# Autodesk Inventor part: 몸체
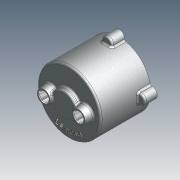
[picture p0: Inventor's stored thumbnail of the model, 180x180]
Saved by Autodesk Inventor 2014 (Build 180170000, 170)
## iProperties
Company: 한국ATC센터
Created: 2012-05
Part Number: 몸체
Document SubType Name: 모델링
Designer: KYOUNG IL JANG
Mass: 471.062 g
Surface Area: 679.308 cm^2
Volume: 173.824 cm^3
Density: 2.71 g/cm^3
Material: 알루미늄-6061
Appearance: 알루미늄 - 평지
변환 표준: STEP AP214IS
파일 이름: C:\Users\SeoGD\Desktop\?쒗뿕\紐몄껜.stp
전처리기: Build: 253, Release: 2010 SP1 - Date: Wed 07/29/2009
전송 단위: 밀리미터
불확실성: 0.01
Author: KYOUNG IL JANG
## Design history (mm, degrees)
sketch "스케치2"
  geometry: C1 r 50 at (0, 0); 1 further point
  constraints: 1 centre point, 1 coincident
  dimensions: "d9" = 100 diameter of C1
extrude "돌출2" new body sketch "스케치2" distance "d10" = 80; taper "d11" = 0 deg
feature "쉘1" dims "d12" = 5
sketch "스케치3" dims "d13" = 55
  geometry: C1 r 7.5 at (27.5, 0); C2 r 12.5 at (27.5, 0); 2 further points
  constraints: 2 centre point, 2 coincident, 2 horizontal alignment, 2 other
  dimensions: "d14" = 15 diameter of C1; "d15" = 25 diameter of C2
extrude "돌출3" join sketch "스케치3" distance "d16" = 12; taper "d17" = -10 deg
hole "구멍2" diameter "d20" = 15; stored, may be unused: countersink angle "d24" = 90 deg, drill point angle "d26" = 118 deg; dims "d18" = 10, "d19" = 10, "d21" = 6, "d22" = 4, "d23" = 2, "d25" = 15
chamfer "모따기1" distance "d27" = 1; stored, may be unused: second distance "d28" = 2, angle "d29" = 45 deg
sketch "스케치4"
  geometry: L1 (0, 0)-(0, 88); L2 (0, 70)-(13.16, 70); L3 (-45, 75)-(45, 75) reference; L4 (-50, 80)-(50, 80) reference; L5 (13.16, 70)-(14.5, 75); L6 (20, 80)-(20, 88); L7 (20, 88)-(0, 88); L8 (20, 80)-(14.5, 75)
  constraints: 12 end point, 3 point on line, 2 perpendicular, 1 vertical
  dimensions: "d34" = 40 diameter of L6 L1; "d35" = 105 deg angle of L5 L3; "d36" = 5 distance between parallel lines of L2 L3; "d37" = 8 distance between parallel lines of L7 L4; "d51" = 29 diameter of L5.end L1
revolve "회전1" sketch "스케치4" stored, may be unused: angle "d38" = 90 deg
hole "구멍3" diameter "d41" = 15; stored, may be unused: countersink angle "d45" = 90 deg, drill point angle "d47" = 0 deg; dims "d39" = 10, "d40" = 10, "d42" = 6, "d43" = 22, "d44" = 13, "d46" = 15
chamfer "모따기2" distance "d48" = 1; stored, may be unused: second distance "d49" = 2, angle "d50" = 45 deg
fillet "모깎기1" dims "d52" = 3
fillet "모깎기2" dims "d53" = 3, "d72" = 0.2
sketch "스케치5"
  geometry: A1 r 50 centre (0, 0) between (50, 0) and (-8.074, 49.344) reference; A2 r 8.5 centre (0, 52) between (8.074, 49.344) and (-8.074, 49.344); 1 further point
  constraints: 5 point on circle, 1 centre point, 1 horizontal alignment
  dimensions: "d54" = 90 deg dimension on point (0, 0) A2.centre A1.start; "d55" = 52 distance of A2.centre point (0, 0); "d56" = 17 diameter of A2
extrude "돌출4" join sketch "스케치5" distance "d57" = 20; taper "d58" = 0 deg
fillet "모깎기3" dims "d59" = 3
hole "구멍4" diameter "d62" = 4.134; stored, may be unused: countersink angle "d66" = 90 deg, drill point angle "d68" = 118 deg; dims "d60" = 10, "d61" = 10, "d63" = 12, "d64" = 22, "d65" = 13, "d67" = 15
sketch "스케치6"
  geometry: C1 r 47 at (0, 0) reference; C2 r 42.5 at (0, 0); 1 further point
  constraints: 1 centre point, 1 coincident, 1 other
  dimensions: "d73" = 85 diameter of C2
feature "엠보싱1" sketch "스케치6" dims "d74" = 1, "d75" = 0
node "솔리드1"
node "솔리드 본체"
node "곡면 본체"
pattern_circular "원형 패턴1" dims "d31" = 360 deg
pattern_circular "원형 패턴2" dims "d70" = 360 deg
node "솔리드2"
